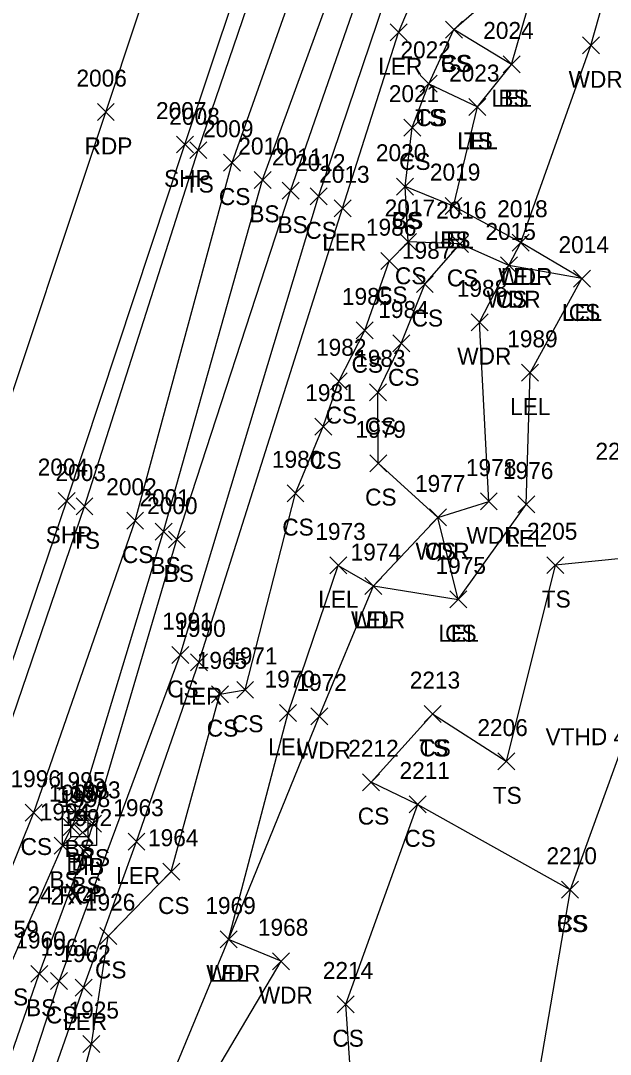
# Model space of a CAD drawing. Extents: x 1483143 to 1488182, y 802902 to 807581.
# Drawn here: x 1487992.8 to 1488062.4, y 806784.9 to 806906.9 of the extents above; entities that cross this region are included whole.
import ezdxf

# ---------------------------------------------------------------- set-up
doc = ezdxf.new("R2010")
doc.units = 0
for name, color, linetype in [('D_A', 7, 'Continuous'), ('D_C', 7, 'Continuous'), ('D_I', 7, 'Continuous'), ('D_TIC', 7, 'Continuous'), ('DS', 7, 'Continuous'), ('L_A', 7, 'Continuous'), ('L_I', 7, 'Continuous'), ('L_TIC', 7, 'Continuous'), ('LARO', 7, 'Continuous'), ('LAWA', 7, 'Continuous'), ('LELB', 7, 'Continuous'), ('M_C', 7, 'Continuous'), ('P_A', 7, 'Continuous'), ('P_I', 7, 'Continuous'), ('P_TIC', 7, 'Continuous'), ('PET', 7, 'Continuous'), ('PSP', 7, 'Continuous')]:
    doc.layers.add(name, color=color, linetype=linetype)

msp = doc.modelspace()

# ---------------------------------------------------------------- linework, layer by layer
at = {"layer": 'D_TIC'}
for points in [[(1487997.82, 806810.7), (1487999.82, 806812.7)], [(1487999.82, 806810.7), (1487997.82, 806812.7)], [(1487999.11, 806810.06), (1488001.11, 806812.06)], [(1488001.11, 806810.06), (1487999.11, 806812.06)]]:
    msp.add_lwpolyline(points, dxfattribs=at)
at = {"layer": 'DS'}
for p, q in [((1487997.73, 806813.53), (1488001.73, 806813.53)), ((1487997.73, 806809.53), (1487997.73, 806813.53)), ((1488001.73, 806813.53), (1488001.73, 806809.53)), ((1487998.73, 806810.53), (1487998.73, 806812.53)), ((1487998.73, 806812.53), (1488000.73, 806812.53)), ((1488000.73, 806812.53), (1488000.73, 806810.53)), ((1487999.74, 806811.54), (1487999.74, 806811.54)), ((1487999.74, 806811.54), (1487999.74, 806811.54)), ((1488000.73, 806810.53), (1487998.73, 806810.53)), ((1488001.73, 806809.53), (1487997.73, 806809.53))]:
    msp.add_line(p, q, dxfattribs=at)
at = {"layer": 'L_TIC'}
for points in [[(1488036.4, 806904.47), (1488038.4, 806906.47)], [(1488038.4, 806904.47), (1488036.4, 806906.47)], [(1488042.93, 806904.8), (1488044.93, 806906.8)], [(1488044.93, 806904.8), (1488042.93, 806906.8)], [(1488042.93, 806904.8), (1488044.93, 806906.8)], [(1488044.93, 806904.8), (1488042.93, 806906.8)], [(1488059.09, 806902.93), (1488061.09, 806904.93)], [(1488061.09, 806902.93), (1488059.09, 806904.93)], [(1488049.72, 806900.7), (1488051.72, 806902.7)], [(1488051.72, 806900.7), (1488049.72, 806902.7)], [(1488049.72, 806900.7), (1488051.72, 806902.7)], [(1488051.72, 806900.7), (1488049.72, 806902.7)], [(1488039.95, 806898.41), (1488041.95, 806900.41)], [(1488041.95, 806898.41), (1488039.95, 806900.41)], [(1488039.95, 806898.41), (1488041.95, 806900.41)], [(1488041.95, 806898.41), (1488039.95, 806900.41)], [(1488045.69, 806895.67), (1488047.69, 806897.67)], [(1488047.69, 806895.67), (1488045.69, 806897.67)], [(1488045.69, 806895.67), (1488047.69, 806897.67)], [(1488047.69, 806895.67), (1488045.69, 806897.67)], [(1488038.01, 806893.24), (1488040.01, 806895.24)], [(1488040.01, 806893.24), (1488038.01, 806895.24)], [(1488012.76, 806890.57), (1488014.76, 806892.57)], [(1488014.76, 806890.57), (1488012.76, 806892.57)], [(1488016.75, 806889.1), (1488018.75, 806891.1)], [(1488018.75, 806889.1), (1488016.75, 806891.1)], [(1488020.34, 806887.06), (1488022.34, 806889.06)], [(1488022.34, 806887.06), (1488020.34, 806889.06)], [(1488023.65, 806885.78), (1488025.65, 806887.78)], [(1488025.65, 806885.78), (1488023.65, 806887.78)], [(1488037.15, 806886.27), (1488039.15, 806888.27)], [(1488039.15, 806886.27), (1488037.15, 806888.27)], [(1488037.15, 806886.27), (1488039.15, 806888.27)], [(1488039.15, 806886.27), (1488037.15, 806888.27)], [(1488026.95, 806885.11), (1488028.95, 806887.11)], [(1488028.95, 806885.11), (1488026.95, 806887.11)], [(1488029.79, 806883.72), (1488031.79, 806885.72)], [(1488031.79, 806883.72), (1488029.79, 806885.72)], [(1488042.87, 806883.98), (1488044.87, 806885.98)], [(1488044.87, 806883.98), (1488042.87, 806885.98)], [(1488042.87, 806883.98), (1488044.87, 806885.98)], [(1488044.87, 806883.98), (1488042.87, 806885.98)], [(1488037.52, 806879.75), (1488039.52, 806881.75)], [(1488039.52, 806879.75), (1488037.52, 806881.75)], [(1488037.52, 806879.75), (1488039.52, 806881.75)], [(1488039.52, 806879.75), (1488037.52, 806881.75)], [(1488050.8, 806879.66), (1488052.8, 806881.66)], [(1488052.8, 806879.66), (1488050.8, 806881.66)], [(1488050.8, 806879.66), (1488052.8, 806881.66)], [(1488052.8, 806879.66), (1488050.8, 806881.66)], [(1488043.65, 806879.5), (1488045.65, 806881.5)], [(1488045.65, 806879.5), (1488043.65, 806881.5)], [(1488043.65, 806879.5), (1488045.65, 806881.5)], [(1488045.65, 806879.5), (1488043.65, 806881.5)], [(1488035.29, 806877.48), (1488037.29, 806879.48)], [(1488037.29, 806877.48), (1488035.29, 806879.48)], [(1488049.41, 806876.98), (1488051.41, 806878.98)], [(1488051.41, 806876.98), (1488049.41, 806878.98)], [(1488049.41, 806876.98), (1488051.41, 806878.98)], [(1488051.41, 806876.98), (1488049.41, 806878.98)], [(1488039.49, 806874.76), (1488041.49, 806876.76)], [(1488041.49, 806874.76), (1488039.49, 806876.76)], [(1488058.03, 806875.42), (1488060.03, 806877.42)], [(1488060.03, 806875.42), (1488058.03, 806877.42)], [(1488058.03, 806875.42), (1488060.03, 806877.42)], [(1488060.03, 806875.42), (1488058.03, 806877.42)], [(1488045.95, 806870.27), (1488047.95, 806872.27)], [(1488047.95, 806870.27), (1488045.95, 806872.27)], [(1488032.4, 806869.31), (1488034.4, 806871.31)], [(1488034.4, 806869.31), (1488032.4, 806871.31)], [(1488036.7, 806867.77), (1488038.7, 806869.77)], [(1488038.7, 806867.77), (1488036.7, 806869.77)], [(1488051.91, 806864.31), (1488053.91, 806866.31)], [(1488053.91, 806864.31), (1488051.91, 806866.31)], [(1488029.34, 806863.31), (1488031.34, 806865.31)], [(1488031.34, 806863.31), (1488029.34, 806865.31)], [(1488033.96, 806862.01), (1488035.96, 806864.01)], [(1488035.96, 806862.01), (1488033.96, 806864.01)], [(1488027.51, 806857.96), (1488029.51, 806859.96)], [(1488029.51, 806857.96), (1488027.51, 806859.96)], [(1488034, 806853.63), (1488036, 806855.63)], [(1488036, 806853.63), (1488034, 806855.63)], [(1488024.23, 806850.09), (1488026.23, 806852.09)], [(1488026.23, 806850.09), (1488024.23, 806852.09)], [(1488047.04, 806849.12), (1488049.04, 806851.12)], [(1488049.04, 806849.12), (1488047.04, 806851.12)], [(1487999.33, 806848.53), (1488001.33, 806850.53)], [(1488001.33, 806848.53), (1487999.33, 806850.53)], [(1488051.46, 806848.77), (1488053.46, 806850.77)], [(1488053.46, 806848.77), (1488051.46, 806850.77)], [(1488005.31, 806846.85), (1488007.31, 806848.85)], [(1488007.31, 806846.85), (1488005.31, 806848.85)], [(1488041.03, 806847.24), (1488043.03, 806849.24)], [(1488043.03, 806847.24), (1488041.03, 806849.24)], [(1488041.03, 806847.24), (1488043.03, 806849.24)], [(1488043.03, 806847.24), (1488041.03, 806849.24)], [(1488008.67, 806845.56), (1488010.67, 806847.56)], [(1488010.67, 806845.56), (1488008.67, 806847.56)], [(1488010.23, 806844.63), (1488012.23, 806846.63)], [(1488012.23, 806844.63), (1488010.23, 806846.63)], [(1488029.27, 806841.58), (1488031.27, 806843.58)], [(1488031.27, 806841.58), (1488029.27, 806843.58)], [(1488054.88, 806841.6), (1488056.88, 806843.6)], [(1488056.88, 806841.6), (1488054.88, 806843.6)], [(1488033.42, 806839.15), (1488035.42, 806841.15)], [(1488035.42, 806839.15), (1488033.42, 806841.15)], [(1488033.42, 806839.15), (1488035.42, 806841.15)], [(1488035.42, 806839.15), (1488033.42, 806841.15)], [(1488043.44, 806837.57), (1488045.44, 806839.57)], [(1488045.44, 806837.57), (1488043.44, 806839.57)], [(1488043.44, 806837.57), (1488045.44, 806839.57)], [(1488045.44, 806837.57), (1488043.44, 806839.57)], [(1488010.64, 806831), (1488012.64, 806833)], [(1488012.64, 806831), (1488010.64, 806833)], [(1488012.83, 806830.14), (1488014.83, 806832.14)], [(1488014.83, 806830.14), (1488012.83, 806832.14)], [(1488015.32, 806826.37), (1488017.32, 806828.37)], [(1488017.32, 806826.37), (1488015.32, 806828.37)], [(1488018.29, 806826.89), (1488020.29, 806828.89)], [(1488020.29, 806826.89), (1488018.29, 806828.89)], [(1488023.35, 806824.16), (1488025.35, 806826.16)], [(1488025.35, 806824.16), (1488023.35, 806826.16)], [(1488027.03, 806823.76), (1488029.03, 806825.76)], [(1488029.03, 806823.76), (1488027.03, 806825.76)], [(1488040.4, 806824.04), (1488042.4, 806826.04)], [(1488042.4, 806824.04), (1488040.4, 806826.04)], [(1488040.4, 806824.04), (1488042.4, 806826.04)], [(1488042.4, 806824.04), (1488040.4, 806826.04)], [(1488049.09, 806818.44), (1488051.09, 806820.44)], [(1488051.09, 806818.44), (1488049.09, 806820.44)], [(1488033.14, 806815.99), (1488035.14, 806817.99)], [(1488035.14, 806815.99), (1488033.14, 806817.99)], [(1488038.63, 806813.37), (1488040.63, 806815.37)], [(1488040.63, 806813.37), (1488038.63, 806815.37)], [(1488038.63, 806813.37), (1488040.63, 806815.37)], [(1488040.63, 806813.37), (1488038.63, 806815.37)], [(1487993.35, 806812.4), (1487995.35, 806814.4)], [(1487995.35, 806812.4), (1487993.35, 806814.4)], [(1487998.54, 806812.18), (1488000.54, 806814.18)], [(1488000.54, 806812.18), (1487998.54, 806814.18)], [(1488000.34, 806811.09), (1488002.34, 806813.09)], [(1488002.34, 806811.09), (1488000.34, 806813.09)], [(1488005.47, 806808.98), (1488007.47, 806810.98)], [(1488007.47, 806808.98), (1488005.47, 806810.98)], [(1487996.75, 806808.49), (1487998.75, 806810.49)], [(1487998.75, 806808.49), (1487996.75, 806810.49)], [(1487999.35, 806807.82), (1488001.35, 806809.82)], [(1488001.35, 806807.82), (1487999.35, 806809.82)], [(1488009.57, 806805.44), (1488011.57, 806807.44)], [(1488011.57, 806805.44), (1488009.57, 806807.44)], [(1488056.62, 806803.31), (1488058.62, 806805.31)], [(1488058.62, 806803.31), (1488056.62, 806805.31)], [(1488056.62, 806803.31), (1488058.62, 806805.31)], [(1488058.62, 806803.31), (1488056.62, 806805.31)], [(1488002.13, 806797.84), (1488004.13, 806799.84)], [(1488004.13, 806797.84), (1488002.13, 806799.84)], [(1488016.34, 806797.44), (1488018.34, 806799.44)], [(1488018.34, 806797.44), (1488016.34, 806799.44)], [(1488016.34, 806797.44), (1488018.34, 806799.44)], [(1488018.34, 806797.44), (1488016.34, 806799.44)], [(1488022.53, 806794.87), (1488024.53, 806796.87)], [(1488024.53, 806794.87), (1488022.53, 806796.87)], [(1487993.99, 806793.38), (1487995.99, 806795.38)], [(1487995.99, 806793.38), (1487993.99, 806795.38)], [(1487996.33, 806792.52), (1487998.33, 806794.52)], [(1487998.33, 806792.52), (1487996.33, 806794.52)], [(1487999.22, 806791.76), (1488001.22, 806793.76)], [(1488001.22, 806791.76), (1487999.22, 806793.76)], [(1488030.14, 806789.78), (1488032.14, 806791.78)], [(1488032.14, 806789.78), (1488030.14, 806791.78)], [(1488000.14, 806785.1), (1488002.14, 806787.1)], [(1488002.14, 806785.1), (1488000.14, 806787.1)]]:
    msp.add_lwpolyline(points, dxfattribs=at)
at = {"layer": 'LARO'}
for points in [[(1487955.83, 806665.17), (1487963.5, 806682.75), (1487969.28, 806707.92), (1487978.63, 806730.1), (1487983.66, 806745.59), (1488000.22, 806792.76), (1488006.47, 806809.98), (1488013.83, 806831.14), (1488030.79, 806884.72), (1488037.4, 806905.47), (1488041.65, 806915.63)], [(1488009.53, 806779.63), (1488017.34, 806798.44), (1488024.35, 806825.16), (1488030.27, 806842.58), (1488034.42, 806840.15), (1488044.44, 806838.57), (1488052.46, 806849.77), (1488052.91, 806865.31), (1488059.03, 806876.42), (1488051.8, 806880.66), (1488043.87, 806884.98), (1488046.69, 806896.67), (1488050.72, 806901.7), (1488054.57, 806915.09)]]:
    msp.add_lwpolyline(points, dxfattribs=at)
at = {"layer": 'LAWA'}
msp.add_lwpolyline([(1488013.56, 806779), (1488023.53, 806795.87), (1488017.34, 806798.44), (1488028.03, 806824.76), (1488034.42, 806840.15), (1488042.03, 806848.24), (1488048.04, 806850.12), (1488046.95, 806871.27), (1488050.41, 806877.98), (1488051.8, 806880.66), (1488060.09, 806903.93), (1488066.6, 806927.09)], dxfattribs=at)
at = {"layer": 'LELB'}
for points in [[(1487827.52, 806379.6), (1487850.09, 806437.73), (1487867.87, 806481.84), (1487885.56, 806528.78), (1487894.77, 806554.11), (1487911.86, 806599.05), (1487925.11, 806635.03), (1487938.6, 806672.73), (1487954.13, 806715.2), (1487966.77, 806750.86), (1487982.82, 806798.37), (1488000.33, 806849.53), (1488013.76, 806891.57), (1488028.96, 806936.12), (1488043.22, 806981), (1488053.37, 807013.21), (1488065.46, 807054.1), (1488079.1, 807097.32), (1488091.92, 807141.06), (1488105.94, 807188.64)], [(1487831.61, 806378.23), (1487855.61, 806436.65), (1487873.41, 806477.14), (1487888.61, 806527.7), (1487900.29, 806552.66), (1487915.56, 806597.3), (1487929.53, 806633.53), (1487942.79, 806670.21), (1487957.7, 806713.57), (1487969.99, 806749.64), (1487987.61, 806796.79), (1487994.35, 806813.4), (1488006.31, 806847.85), (1488017.75, 806890.1), (1488033.51, 806934.67), (1488047.05, 806979.87), (1488058.1, 807011.89), (1488070.58, 807052.35), (1488082.44, 807096.83), (1488095.42, 807139.95), (1488114.02, 807186.94)], [(1487835.19, 806376.59), (1487859.78, 806434.97), (1487877.62, 806477.28), (1487892.57, 806526.23), (1487904.08, 806551.45), (1487919.68, 806595.15), (1487934.47, 806632.17), (1487947.69, 806668.31), (1487962.32, 806711.59), (1487973.69, 806748.32), (1487991.68, 806795.65), (1487997.75, 806809.49), (1487999.54, 806813.18), (1488009.67, 806846.56), (1488021.34, 806888.06), (1488037.67, 806932.78), (1488051.91, 806977.51), (1488062.67, 807010.29), (1488074.95, 807051.31), (1488088, 807095.72), (1488100.03, 807138.12), (1488122.67, 807183.2)], [(1487837.5, 806376), (1487863.45, 806433.38), (1487880.32, 806475.86), (1487894.61, 806525.53), (1487906.02, 806551.4), (1487922.48, 806594.15), (1487937, 806631.99), (1487949.11, 806668.02), (1487964.79, 806711), (1487978.4, 806746.47), (1487994.99, 806794.38), (1488000.35, 806808.82), (1488001.34, 806812.09), (1488011.23, 806845.63), (1488024.65, 806886.78), (1488040.19, 806931.5), (1488054.27, 806976.88), (1488065.68, 807009.57), (1488076.91, 807050.77), (1488090.18, 807095.37), (1488103.15, 807137.16), (1488127.49, 807179.54)], [(1487839.66, 806374.66), (1487865.87, 806433.14), (1487881.15, 806476.22), (1487897.55, 806523.91), (1487908.57, 806550.53), (1487926.89, 806591.97), (1487940.49, 806630.59), (1487952.54, 806666.3), (1487966.7, 806710.04), (1487981.74, 806745.96), (1487997.33, 806793.52), (1488011.64, 806832), (1488027.95, 806886.11), (1488041.92, 806927.39), (1488045.38, 806935.91), (1488056.2, 806975.87), (1488068.38, 807008.79), (1488080.46, 807050.29), (1488092.26, 807094.39), (1488105.79, 807135.26), (1488129.48, 807176.06)], [(1488107.24, 807063.62), (1488102.78, 807019.53), (1488102.52, 806993.48), (1488098.25, 806971.93), (1488100.18, 806941.81), (1488099.28, 806926.81), (1488086.46, 806896.83), (1488081.97, 806885.84), (1488071.39, 806887.6), (1488071.71, 806872.37), (1488064.05, 806852.05), (1488068.8, 806843.92), (1488067.03, 806830.27), (1488057.62, 806804.31), (1488039.63, 806814.37), (1488034.14, 806816.99), (1488041.4, 806825.04)], [(1487996.58, 806769.24), (1488001.14, 806786.1), (1488003.13, 806798.84), (1488010.57, 806806.44), (1488016.32, 806827.37), (1488019.29, 806827.89), (1488025.23, 806851.09), (1488028.51, 806858.96), (1488030.34, 806864.31), (1488033.4, 806870.31), (1488036.29, 806878.48), (1488038.52, 806880.75), (1488038.15, 806887.27), (1488039.01, 806894.24), (1488040.95, 806899.41), (1488043.93, 806905.8), (1488054.57, 806915.09)], [(1488050.72, 806901.7), (1488043.93, 806905.8)], [(1488040.95, 806899.41), (1488046.69, 806896.67)], [(1488043.87, 806884.98), (1488038.15, 806887.27)], [(1488044.44, 806838.57), (1488042.03, 806848.24), (1488035, 806854.63), (1488034.96, 806863.01), (1488037.7, 806868.77), (1488040.49, 806875.76), (1488044.65, 806880.5)], [(1488059.03, 806876.42), (1488050.41, 806877.98), (1488044.65, 806880.5), (1488038.52, 806880.75)], [(1488068.8, 806843.92), (1488055.88, 806842.6), (1488050.09, 806819.44), (1488041.4, 806825.04)], [(1488039.63, 806814.37), (1488031.14, 806790.78), (1488032.93, 806764.39), (1488017.53, 806734.89), (1488014.76, 806696.96), (1488001.7, 806658.62), (1487995.09, 806633.92), (1487984.98, 806604.57), (1487980.48, 806572.93), (1487969.96, 806553.52), (1487953.46, 806540.54), (1487965.47, 806536.44), (1487984.45, 806521.74), (1488004.88, 806498.25)], [(1488057.62, 806804.31), (1488053.28, 806778.75), (1488055.57, 806759.29), (1488045.22, 806727.88), (1488037.59, 806692.17), (1488022.17, 806654.43), (1488019.2, 806624.46), (1488014.13, 806598.44), (1488002.07, 806550.47)]]:
    msp.add_lwpolyline(points, dxfattribs=at)
at = {"layer": 'P_TIC'}
for points in [[(1488001.85, 806895.07), (1488003.85, 806897.07)], [(1488003.85, 806895.07), (1488001.85, 806897.07)], [(1488011.19, 806891.24), (1488013.19, 806893.24)], [(1488013.19, 806891.24), (1488011.19, 806893.24)], [(1487997.23, 806849.18), (1487999.23, 806851.18)], [(1487999.23, 806849.18), (1487997.23, 806851.18)]]:
    msp.add_lwpolyline(points, dxfattribs=at)
at = {"layer": 'PET'}
msp.add_lwpolyline([(1487817.05, 806384.04), (1487839.67, 806441.4), (1487857.48, 806486.15), (1487875.5, 806533.55), (1487884.95, 806558.16), (1487901.52, 806603.65), (1487914.56, 806639.6), (1487927.99, 806676.8), (1487943.06, 806720.01), (1487955.19, 806754.64), (1487971.37, 806801.63), (1487988.85, 806854.11), (1488002.85, 806896.07), (1488017.7, 806940.87), (1488031.56, 806984.9), (1488041.8, 807017.08), (1488054.37, 807058.25), (1488067.6, 807101.48), (1488080.81, 807144.82), (1488095.07, 807192.49)], dxfattribs=at)
at = {"layer": 'PSP'}
msp.add_lwpolyline([(1487825.55, 806380.21), (1487847.81, 806437.56), (1487866.19, 806483.39), (1487884.04, 806529.78), (1487893.44, 806554.46), (1487910.05, 806599.89), (1487923.16, 806635.65), (1487936.98, 806673.57), (1487951.99, 806715.79), (1487964.7, 806751.7), (1487980.81, 806798.97), (1487998.23, 806850.18), (1488012.19, 806892.24), (1488027.11, 806936.91), (1488041.21, 806981.53), (1488051.31, 807013.35), (1488064.14, 807054.93), (1488077.14, 807097.61), (1488090.36, 807141.77), (1488104.31, 807189.57)], dxfattribs=at)

# ---------------------------------------------------------------- texts
at = {"layer": 'D_A'}
for s, p in [('P', (1487998.2, 806806.7)), ('DI', (1487998.79, 806806.54)), ('DIB', (1487998.21, 806806.06))]:
    msp.add_text(s, height=2, dxfattribs=at).set_placement(p)
at = {"layer": 'D_C'}
for s, p in [('24 RCP', (1487993.62, 806802.7)), ("2'X4'", (1487996.33, 806802.54))]:
    msp.add_text(s, height=2, dxfattribs=at).set_placement(p)
at = {"layer": 'D_I'}
for s, p in [('1999', (1487996.12, 806814.7)), ('1997', (1487997.04, 806814.54)), ('1998', (1487997.42, 806814.06))]:
    msp.add_text(s, height=2, dxfattribs=at).set_placement(p)
at = {"layer": 'L_A'}
for s, p in [('LER', (1488034.99, 806900.47)), ('CS', (1488042.37, 806900.8)), ('BS', (1488042.37, 806900.8)), ('WDR', (1488057.45, 806898.93)), ('LEL', (1488048.35, 806896.7)), ('BS', (1488049.16, 806896.7)), ('TS', (1488039.36, 806894.41)), ('CS', (1488039.39, 806894.41)), ('LEL', (1488044.32, 806891.67)), ('TS', (1488045.1, 806891.67)), ('CS', (1488037.45, 806889.24)), ('TS', (1488012.17, 806886.57)), ('CS', (1488016.19, 806885.1)), ('BS', (1488019.78, 806883.06)), ('CS', (1488036.59, 806882.27)), ('BS', (1488036.59, 806882.27)), ('BS', (1488023.1, 806881.78)), ('CS', (1488026.39, 806881.11)), ('LER', (1488028.38, 806879.72)), ('LEL', (1488041.51, 806879.98)), ('BS', (1488042.31, 806879.98)), ('CS', (1488036.96, 806875.75)), ('CS', (1488036.96, 806875.75)), ('CS', (1488043.09, 806875.5)), ('CS', (1488043.09, 806875.5)), ('WDR', (1488049.16, 806875.66)), ('LEL', (1488049.44, 806875.66)), ('CS', (1488034.73, 806873.48)), ('WDR', (1488047.77, 806872.98)), ('CS', (1488048.85, 806872.98)), ('LEL', (1488056.66, 806871.42)), ('CS', (1488057.47, 806871.42)), ('CS', (1488038.93, 806870.76)), ('WDR', (1488044.31, 806866.27)), ('CS', (1488031.84, 806865.31)), ('CS', (1488036.14, 806863.77)), ('LEL', (1488050.55, 806860.31)), ('CS', (1488028.78, 806859.31)), ('CS', (1488033.4, 806858.01)), ('CS', (1488026.95, 806853.96)), ('CS', (1488033.44, 806849.63)), ('CS', (1488023.67, 806846.09)), ('TS', (1487998.74, 806844.53)), ('WDR', (1488045.4, 806845.12)), ('LEL', (1488050.1, 806844.77)), ('WDR', (1488039.39, 806843.24)), ('CS', (1488040.47, 806843.24)), ('CS', (1488004.75, 806842.85)), ('BS', (1488008.11, 806841.56)), ('BS', (1488009.67, 806840.63)), ('LEL', (1488027.91, 806837.58)), ('TS', (1488054.29, 806837.6)), ('WDR', (1488031.78, 806835.15)), ('LEL', (1488032.06, 806835.15)), ('LEL', (1488042.08, 806833.57)), ('CS', (1488042.88, 806833.57)), ('CS', (1488010.08, 806827)), ('LER', (1488011.41, 806826.14)), ('CS', (1488014.76, 806822.37)), ('CS', (1488017.73, 806822.89)), ('LEL', (1488021.99, 806820.16)), ('TS', (1488039.81, 806820.04)), ('CS', (1488039.84, 806820.04)), ('WDR', (1488025.39, 806819.76)), ('TS', (1488048.5, 806814.44)), ('CS', (1488032.58, 806811.99)), ('CS', (1488038.07, 806809.37)), ('CS', (1488038.07, 806809.37)), ('CS', (1487992.79, 806808.4)), ('BS', (1487997.98, 806808.18)), ('BS', (1487999.78, 806807.09)), ('BS', (1487996.19, 806804.49)), ('LER', (1488004.06, 806804.98)), ('BS', (1487998.8, 806803.82)), ('CS', (1488009.01, 806801.44)), ('CS', (1488056.06, 806799.31)), ('BS', (1488056.06, 806799.31)), ('CS', (1488001.57, 806793.84)), ('WDR', (1488014.7, 806793.44)), ('LEL', (1488014.98, 806793.44)), ('BS', (1487990.12, 806790.65)), ('WDR', (1488020.89, 806790.87)), ('BS', (1487993.43, 806789.38)), ('CS', (1487995.77, 806788.52)), ('LER', (1487997.8, 806787.76)), ('CS', (1488029.58, 806785.78))]:
    msp.add_text(s, height=2, dxfattribs=at).set_placement(p)
at = {"layer": 'L_I'}
for s, p in [('2024', (1488047.38, 806904.7)), ('2024', (1488047.38, 806904.7)), ('2022', (1488037.61, 806902.41)), ('2022', (1488037.61, 806902.41)), ('2023', (1488043.35, 806899.67)), ('2023', (1488043.35, 806899.67)), ('2021', (1488036.24, 806897.24)), ('2008', (1488010.34, 806894.57)), ('2009', (1488014.32, 806893.1)), ('2010', (1488018.48, 806891.06)), ('2011', (1488022.45, 806889.78)), ('2020', (1488034.72, 806890.27)), ('2020', (1488034.72, 806890.27)), ('2012', (1488025.18, 806889.11)), ('2013', (1488028.02, 806887.72)), ('2019', (1488041.09, 806887.98)), ('2019', (1488041.09, 806887.98)), ('2017', (1488035.75, 806883.75)), ('2017', (1488035.75, 806883.75)), ('2016', (1488041.82, 806883.5)), ('2016', (1488041.82, 806883.5)), ('2018', (1488049.03, 806883.66)), ('2018', (1488049.03, 806883.66)), ('1986', (1488033.54, 806881.48)), ('2015', (1488047.64, 806880.98)), ('2015', (1488047.64, 806880.98)), ('1987', (1488037.79, 806878.76)), ('2014', (1488056.26, 806879.42)), ('2014', (1488056.26, 806879.42)), ('1988', (1488044.26, 806874.27)), ('1985', (1488030.71, 806873.31)), ('1984', (1488035, 806871.77)), ('1989', (1488050.21, 806868.31)), ('1982', (1488027.65, 806867.31)), ('1983', (1488032.27, 806866.01)), ('1981', (1488026.38, 806861.96)), ('1979', (1488032.3, 806857.63)), ('1980', (1488022.45, 806854.09)), ('2200', (1488060.62, 806855.05)), ('1978', (1488045.34, 806853.12)), ('1976', (1488049.71, 806852.77)), ('2003', (1487996.91, 806852.53)), ('2002', (1488002.9, 806850.85)), ('1977', (1488039.33, 806851.24)), ('1977', (1488039.33, 806851.24)), ('2001', (1488006.82, 806849.56)), ('2000', (1488007.72, 806848.63)), ('1973', (1488027.57, 806845.58)), ('2205', (1488052.54, 806845.6)), ('1974', (1488031.73, 806843.15)), ('1974', (1488031.73, 806843.15)), ('1975', (1488041.75, 806841.57)), ('1975', (1488041.75, 806841.57)), ('1991', (1488009.51, 806835)), ('1990', (1488011.05, 806834.14)), ('1971', (1488017.16, 806830.89)), ('1965', (1488013.58, 806830.37)), ('1970', (1488021.57, 806828.16)), ('1972', (1488025.34, 806827.76)), ('2213', (1488038.71, 806828.04)), ('2213', (1488038.71, 806828.04)), ('2206', (1488046.69, 806822.44)), ('2212', (1488031.45, 806819.99)), ('2211', (1488037.5, 806817.37)), ('2211', (1488037.5, 806817.37)), ('1996', (1487991.6, 806816.4)), ('1995', (1487996.85, 806816.18)), ('1993', (1487998.64, 806815.09)), ('1994', (1487995.05, 806812.49)), ('1963', (1488003.73, 806812.98)), ('1992', (1487997.66, 806811.82)), ('1964', (1488007.83, 806809.44)), ('2210', (1488054.84, 806807.31)), ('2210', (1488054.84, 806807.31)), ('1926', (1488000.38, 806801.84)), ('1969', (1488014.59, 806801.44)), ('1969', (1488014.59, 806801.44)), ('1959', (1487988.98, 806798.65)), ('1968', (1488020.79, 806798.87)), ('1960', (1487992.17, 806797.38)), ('1961', (1487995.16, 806796.52)), ('1962', (1487997.48, 806795.76)), ('2214', (1488028.45, 806793.78)), ('1925', (1487998.45, 806789.1))]:
    msp.add_text(s, height=2, dxfattribs=at).set_placement(p)
at = {"layer": 'M_C'}
msp.add_text('VTHD 4X4" CONCRETE 6"ABG', height=2, dxfattribs=at).set_placement((1488054.73, 806821.36))
at = {"layer": 'P_A'}
for s, p in [('RDP', (1488000.34, 806891.07)), ('SHP', (1488009.72, 806887.24)), ('SHP', (1487995.76, 806845.18))]:
    msp.add_text(s, height=2, dxfattribs=at).set_placement(p)
at = {"layer": 'P_I'}
for s, p in [('2006', (1487999.38, 806899.07)), ('2007', (1488008.77, 806895.24)), ('2004', (1487994.81, 806853.18))]:
    msp.add_text(s, height=2, dxfattribs=at).set_placement(p)

doc.saveas('drawing.dxf')
